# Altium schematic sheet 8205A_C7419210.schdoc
size 127 x 101 mm
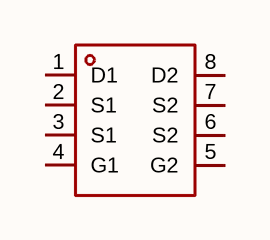
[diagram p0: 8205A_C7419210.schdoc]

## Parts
Q?  8205a_c7419210  [TSSOP-8_L4.4-W3.0-P0.65-LS6.4-TL]  (value not drawn)

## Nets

Not connected (* = marked no-connect by the designer): Q? 1(D1) 2(S1) 3(S1) 4(G1) 5(G2) 6(S2) 7(S2) 8(D2)

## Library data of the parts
Q? = 8205a_c7419210: 漏源电压(Vdss):20V;连续漏极电流(Id):6A;导通电阻(RDS(on)@Vgs,Id):19mΩ@6A;功率:1.5W;阈值电压(Vgs(th)@Id):1.2V@250uA;; Manufacturer: TECH PUBLIC(台舟); ManufacturerPart: 8205A; AddInBom: yes; ModelId: 58a414fcc9ba423684db74486b97e851; ModelTransform: 118.11,251.968,0,270,0,0,0,0,0; Drain Source Voltage (Vdss): 20V; Continuous Drain Current (Id): 6A; Power Dissipation (Pd): 1.5W; Total Gate Charge (Qg@Vgs): 2.3nC@4.5V; Input Capacitance (Ciss@Vds): 600pF; Reverse Transfer Capacitance (Crss@Vds): 140pF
